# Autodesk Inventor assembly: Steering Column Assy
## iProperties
Shininess: 64.0
Length Units: 11269
Angle Units: 11279
Time Units: 11290
Mass Units: 11283
Length Display Precision: 3
Angle Display Precision: 2
Compacted: True
Created: 2004-03
Part Number: Steering Column Assy
Document SubType Name: Assembly
Designer: rak
Manufacturer: Standard
Standards Organization: Custom
Density: 0.0
Volumn: 0.0
Area: 0.0
PropertySet Name: Model Information
Control State: 0
Master: False
Checked Out: False
Author: rak
